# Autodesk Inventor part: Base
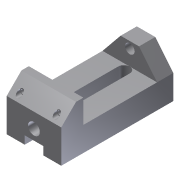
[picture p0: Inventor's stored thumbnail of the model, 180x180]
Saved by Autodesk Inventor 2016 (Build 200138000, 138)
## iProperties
Shininess: 77.0
Length Units: 11269
Angle Units: 11279
Time Units: 11290
Mass Units: 11283
Length Display Precision: 3
Angle Display Precision: 2
Created: 2002-02
Part Number: Base
Document SubType Name: Modeling
Designer: ***
Density: 1 g/cm^3
Material: Generic
Appearance: Default
Density: 0.0
Volumn: 0.0
Area: 0.0
PropertySet Name: Model Information
Control State: 0
Master: False
Checked Out: False
Author: ***
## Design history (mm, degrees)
sketch "Sketch2"
  geometry: L1 (-63.961, -4.254)-(-63.961, -37.254); L2 (-63.961, -37.254)-(88.039, -37.254); L3 (88.039, -37.254)-(88.039, 7.746); L4 (88.039, 7.746)-(68.039, 27.746); L5 (68.039, 27.746)-(58.039, 27.746); L6 (58.039, 27.746)-(58.039, -4.254); L7 (58.039, -4.254)-(-63.961, -4.254)
  constraints: 14 end point, 4 parallel, 1 perpendicular, 1 vertical
  dimensions: "d7" = 10 distance of L4.end L5.end; "d8" = 135 deg angle of L3 L4; "d9" = 33 distance of L1.start L1.end; "d10" = 152 distance of L1.end L2.end; "d11" = 65 distance between parallel lines of L5 L2; "d21" = 30 distance between parallel lines of L3 L6
extrude "Extrusion1" new body sketch "Sketch2" stored distance "d13" = 74; taper "d14" = 0 deg
sketch "Sketch3"
  geometry: L1 (0, 74)-(0, 0) reference; L2 (0, 0)-(-30, 24.5); L3 (-30, 24.5)-(-30, 49.5); L4 (-30, 49.5)-(0, 74); C1 r 6.5 at (-21, 37)
  constraints: 6 end point, 1 centre point, 1 equal length, 1 parallel
  dimensions: "d15" = 25 distance of L2.end L3.end; "d16" = 30 distance between parallel lines of L3 L1; "d17" = 13 diameter of C1; "d18" = 9 distance from line of L3 C1.centre
extrude "Extrusion2" join sketch "Sketch3" distance "d19" = 22; taper "d20" = 0 deg
sketch "Sketch4"
  geometry: L1 (0, 0)-(0, 74) reference; L2 (0, 0)-(45, 0) reference; C1 r 8 at (25, 37)
  constraints: 1 centre point
  dimensions: "d22" = 16 diameter of C1; "d23" = 25 distance from line of L1 C1.centre; "d24" = 37 distance from line of L2 C1.centre
extrude "Extrusion3" cut sketch "Sketch4" distance "d25" = 13; taper "d26" = 0 deg
sketch "Sketch5"
  geometry: L1 (45, 74)-(0, 74) reference; L2 (65, 0)-(65, 74) reference; 1 further point
  dimensions: "d27" = 12 distance from line of point (51, 62) L1; "d28" = 14 distance from line of L2 point (51, 62)
hole "Hole1" sketch "Sketch5" at (51, 62) diameter "d29" = 6; stored, may be unused: countersink angle "d33" = 82 deg, drill point angle "d35" = 0 deg; dims "d30" = 6, "d31" = 8, "d32" = 10, "d34" = 30
mirror "Mirror1"
sketch "Sketch6"
  geometry: L1 (100, 0)-(100, 74) reference; L2 (100, 74)-(0, 74) reference; L3 (14, 45)-(92, 45); L4 (92, 29)-(14, 29); A1 r 8 centre (92, 37) between (92, 29) and (92, 45); A2 r 8 centre (14, 37) between (14, 45) and (14, 29)
  constraints: 4 end point, 4 point on circle, 4 tangent, 2 centre point, 1 horizontal, 1 parallel
  dimensions: "d36" = 8 radius of A2; "d37" = 78 distance of L4.start L4.end; "d38" = 8 distance from line of L1 A1.centre; "d39" = 37 distance from line of L2 A2.centre
extrude "Extrusion4" cut sketch "Sketch6" stored distance "d40" = 13; taper "d41" = 0 deg
sketch "Sketch7"
  geometry: L1 (0, 49.5)-(11, 49.5); L2 (11, 49.5)-(11, 24.5); L3 (11, 24.5)-(0, 24.5); L4 (0, 24.5)-(0, 49.5); L5 (45, 74)-(0, 74) reference; L6 (0, 0)-(0, 74) reference
  constraints: 8 end point, 2 parallel, 1 collinear, 1 horizontal, 1 perpendicular
  dimensions: "d42" = 25 distance of L3.end L1.start; "d43" = 11 distance of L1.start L1.end; "d44" = 24.5 distance between parallel lines of L5 L1
extrude "Extrusion5" cut sketch "Sketch7" stored distance "d45" = 13; taper "d46" = 0 deg
body "Solid1"
